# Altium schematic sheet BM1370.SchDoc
size A3; SheetNumber: 4; SheetTotal: 16
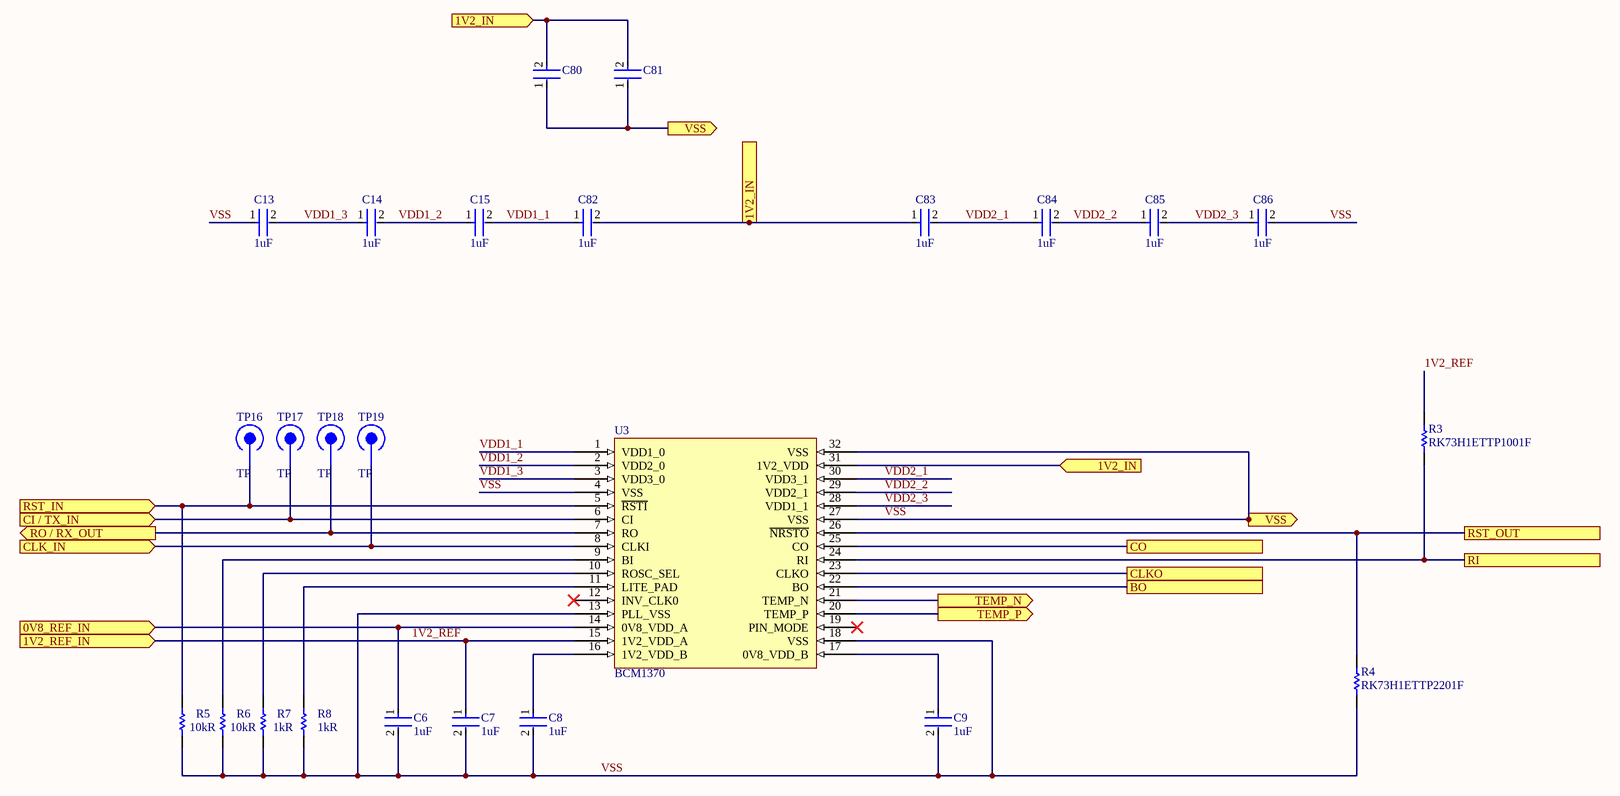
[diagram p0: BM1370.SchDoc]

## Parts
C6  value 1uF  [FP-0402-L_1_0_0_05-W_0_5-MFG]  (hidden comment: EMK105BJ105KV-F)
C7  value 1uF  [FP-0402-L_1_0_0_05-W_0_5-MFG]  (hidden comment: EMK105BJ105KV-F)
C8  value 1uF  [FP-0402-L_1_0_0_05-W_0_5-MFG]  (hidden comment: EMK105BJ105KV-F)
C9  value 1uF  [FP-0402-L_1_0_0_05-W_0_5-MFG]  (hidden comment: EMK105BJ105KV-F)
C13  value 1uF  [FP-0402-L_1_0_0_05-W_0_5-MFG]  (hidden comment: EMK105BJ105KV-F)
C14  value 1uF  [FP-0402-L_1_0_0_05-W_0_5-MFG]  (hidden comment: EMK105BJ105KV-F)
C15  value 1uF  [FP-0402-L_1_0_0_05-W_0_5-MFG]  (hidden comment: EMK105BJ105KV-F)
C80  GRM31CR60J107MEA8K  [FP-GRM31C-0_3-e0_3_0_8-IPC_A]  (value not drawn)
C81  GRM31CR60J107MEA8K  [FP-GRM31C-0_3-e0_3_0_8-IPC_A]  (value not drawn)
C82  value 1uF  [FP-0402-L_1_0_0_05-W_0_5-MFG]  (hidden comment: EMK105BJ105KV-F)
C83  value 1uF  [FP-0402-L_1_0_0_05-W_0_5-MFG]  (hidden comment: EMK105BJ105KV-F)
C84  value 1uF  [FP-0402-L_1_0_0_05-W_0_5-MFG]  (hidden comment: EMK105BJ105KV-F)
C85  value 1uF  [FP-0402-L_1_0_0_05-W_0_5-MFG]  (hidden comment: EMK105BJ105KV-F)
C86  value 1uF  [FP-0402-L_1_0_0_05-W_0_5-MFG]  (hidden comment: EMK105BJ105KV-F)
R3  RK73H1ETTP1001F  [RESC1005X40X25LL10T10]
R4  RK73H1ETTP2201F  [RK73H1ETTP2201F-Footprint-1]
R5  value 10kR  [RESC1005X40X25LL10T10]  (hidden comment: RK73H1ETTP1002F)
R6  value 10kR  [RESC1005X40X25LL10T10]  (hidden comment: RK73H1ETTP1002F)
R7  value 1kR  [RESC1005X40X25LL10T10]  (hidden comment: RK73H1ETTP1001F)
R8  value 1kR  [RESC1005X40X25LL10T10]  (hidden comment: RK73H1ETTP1001F)
TP16  TP  [TP-Footprint-1]
TP17  TP  [TP-Footprint-1]
TP18  TP  [TP-Footprint-1]
TP19  TP  [TP-Footprint-1]
U3  BCM1370  [BCM1370-Footprint-1]

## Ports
0V8_REF_IN (in), 1V2_IN (in), 1V2_REF_IN (in), BO, CI / TX_IN (in), CLK_IN (in), CLKO, CO, RI, RO / RX_OUT (out), RST_IN (in), RST_OUT, TEMP_N (out), TEMP_P (out), VSS (out)

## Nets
0V8_REF_IN: C6.1 U3.14(0V8_VDD_A) ; port 0V8_REF_IN
1V2_IN: C80.2 C81.2 C82.2 C83.1 U3.31(1V2_VDD) ; port 1V2_IN
1V2_REF: C7.1 R3.2 U3.15(1V2_VDD_A) ; port 1V2_REF_IN
BO: U3.22(BO) ; port BO
CI / TX_IN: TP17.1 U3.6(CI) ; port CI / TX_IN
CLK_IN: TP19.1 U3.8(CLKI) ; port CLK_IN
CLKO: U3.23(CLKO) ; port CLKO
CO: U3.25(CO) ; port CO
RI: R3.1 U3.24(RI) ; port RI
RO / RX_OUT: TP18.1 U3.7(RO) ; port RO / RX_OUT
RST_IN: R5.2 TP16.1 U3.5(~{RSTI}) ; port RST_IN
RST_OUT: R4.2 U3.26(~{NRSTO}) ; port RST_OUT
TEMP_N: U3.21(TEMP_N) ; port TEMP_N
TEMP_P: U3.20(TEMP_P) ; port TEMP_P
VDD1_1: C15.2 C82.1 U3.1(VDD1_0)
VDD1_2: C14.2 C15.1 U3.2(VDD2_0)
VDD1_3: C13.2 C14.1 U3.3(VDD3_0)
VDD2_1: C83.2 C84.1 U3.30(VDD3_1)
VDD2_2: C84.2 C85.1 U3.29(VDD2_1)
VDD2_3: C85.2 C86.1 U3.28(VDD1_1)
VSS: C6.2 C7.2 C8.2 C9.2 C13.1 C80.1 C81.1 C86.2 R4.1 R5.1 R6.1 R7.1 R8.1 U3.4(VSS) U3.13(PLL_VSS) U3.18(VSS) U3.27(VSS) U3.32(VSS) ; port VSS
NetC8_1: C8.1 U3.16(1V2_VDD_B)
NetC9_1: C9.1 U3.17(0V8_VDD_B)
NetR6_2: R6.2 U3.9(BI)
NetR7_2: R7.2 U3.10(ROSC_SEL)
NetR8_2: R8.2 U3.11(LITE_PAD)

Not connected (* = marked no-connect by the designer): U3 12(INV_CLK0)* 19(PIN_MODE)*

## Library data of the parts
C6-C9 C13-C15 C82-C86 = CMP-x00039-4: Ceramic Capacitor, Multilayer, Ceramic, 16V, 10% +Tol, 10% -Tol, X5R, 15% TC, 1uF, Surface Mount, 0402; Manufacturer: Taiyo Yuden; Vendor: TTI; Template: TY_0402; Reel Width: 8mm
C80 C81 = CMP-x00203-1: Ceramic Capacitor, Multilayer, Ceramic, 6.3V, 20% +Tol, 20% -Tol, X5R, 15% TC, 100uF, Surface Mount, 1206; Manufacturer: Murata; Template: MR_1206_C
R3 = CMP-x00163-1: Fixed Resistor, Metal Glaze/thick Film, 0.1W, 1000ohm, 75V, 1% +/-Tol, 100ppm/Cel, Surface Mount, 0402; Value: 1kR
R4 = CMP-x00008-3: Fixed Resistor, Metal Glaze/thick Film, 0.1W, 2200ohm, 75V, 1% +/-Tol, 100ppm/Cel, Surface Mount, 0402; Manufacturer: KOA Speer; Value: 2.2kΩ; Reel Width: 8mm; Rating: 100mW; Template: KS_0402; Vendor: TTI
R5 R6 = CMP-x00150-1: Fixed Resistor, Metal Glaze/thick Film, 0.1W, 10000ohm, 75V, 1% +/-Tol, 100ppm/Cel, Surface Mount, 0402
R7 R8 = CMP-x00163-1: Fixed Resistor, Metal Glaze/thick Film, 0.1W, 1000ohm, 75V, 1% +/-Tol, 100ppm/Cel, Surface Mount, 0402
TP16-TP19 = CMP-001-0086-3: digital shovel test point
U3 = CMP-x00104-5: BCM1370 Miner Chip; Manufacturer: Bitmain; Template: BM_QFN32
